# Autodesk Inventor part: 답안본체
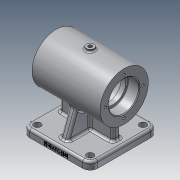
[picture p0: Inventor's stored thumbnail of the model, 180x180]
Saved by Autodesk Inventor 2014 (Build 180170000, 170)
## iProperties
Created: 2019-06
Part Number: 답안본체
Material: 알루미늄 6061
Document SubType Name: Modeling
Designer: net
Density: 2.71 g/cm^3
Appearance: 알루미늄 - 평지
Mass: 612.561 g
Surface Area: 622.973 cm^2
Volume: 226.037 cm^3
Author: net
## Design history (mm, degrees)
sketch "스케치1"
  geometry: C1 r 32 at (0, 0); 1 further point
  constraints: 1 centre point, 1 coincident
  dimensions: "d0" = 64 diameter of C1
extrude "돌출1" new body sketch "스케치1" stored distance "d1" = 90; taper "d2" = 0 deg
sketch "스케치2"
  geometry: L1 (-32, -45)-(32, -45) reference; L2 (32, 45)-(-32, 45) reference; L3 (0, 45)-(0, -45); L4 (0, 45)-(20, 45); L5 (20, 45)-(20, 30.6); L6 (19.4, 30)-(17, 30); L7 (17, 30)-(17, 24); L8 (17, 24)-(25, 24); L9 (25, 24)-(25, -24); L10 (25, -24)-(17, -24); L11 (17, -24)-(17, -30); L12 (17, -30)-(19.4, -30); L13 (20, -30.6)-(20, -45); L14 (20, -45)-(0, -45); A1 r 0.6 centre (19.4, 30.6) between (19.4, 30) and (20, 30.6); A2 r 0.6 centre (19.4, -30.6) between (20, -30.6) and (19.4, -30); 3 further points
  constraints: 24 end point, 6 parallel, 6 point on line, 4 point on circle, 4 tangent, 3 perpendicular, 2 centre point, 2 midpoint, 1 collinear, 1 equal radius
  dimensions: "d3" = 15 distance of L4.end point (20, 30); "d4" = 15 distance of point (20, -30) L13.end; "d5" = 6 distance of L10.end L11.end; "d6" = 6 distance of L6.end L7.end; "d7" = 40 diameter of L5 L3; "d8" = 40 diameter of L13 L3; "d9" = 34 diameter of L11 L3; "d10" = 34 diameter of L7 L3; "d11" = 50 diameter of L9 L3; "d12" = 0.6 radius of A1
revolve "회전1" sketch "스케치2" stored, may be unused: angle "d13" = 90 deg
chamfer "모따기1" distance "d14" = 1; stored, may be unused: second distance "d15" = 2, angle "d16" = 45 deg
node "작업 평면1"
sketch "스케치3"
  geometry: C1 r 5 at (0, 0); 1 further point
  constraints: 1 centre point, 1 coincident
  dimensions: "d18" = 10 diameter of C1
extrude "돌출2" join sketch "스케치3" stored distance "d19" = 90; taper "d20" = 0 deg
sketch "스케치4"
  geometry: C1 r 5 at (0, 0) reference; 1 further point
  constraints: 1 coincident
hole "구멍1" sketch "스케치4" at (0, 0) diameter "d21" = 4.917; stored, may be unused: countersink angle "d25" = 90 deg, drill point angle "d27" = 118 deg; dims "d22" = 6, "d23" = 4, "d24" = 2, "d26" = 20
fillet "모깎기1" dims "d28" = 2
sketch "스케치5"
  geometry: C1 r 32 at (0, 0) reference; 1 further point
  constraints: 1 horizontal alignment
  dimensions: "d29" = 25 distance of C1.centre point (-25, 0)
hole "구멍2" sketch "스케치5" at (-25, 0) diameter "d30" = 3.242; stored, may be unused: countersink angle "d34" = 90 deg, drill point angle "d36" = 118 deg; dims "d31" = 7, "d32" = 4, "d33" = 2, "d35" = 9
node "작업 평면2"
sketch "스케치6"
  geometry: L1 (45, 45)-(-45, 45); L2 (-45, 45)-(-45, -45); L3 (-45, -45)-(45, -45); L4 (45, -45)-(45, 45); L5 (45, 45)-(-45, -45); L6 (-45, 45)-(45, -45); 1 further point
  constraints: 12 end point, 2 midpoint, 2 parallel, 1 horizontal, 1 perpendicular
  dimensions: "d41" = 90 distance of L3.end L2.end; "d42" = 90 distance of L3.end L1.start
extrude "돌출3" join sketch "스케치6" distance "d43" = 10; taper "d44" = 0 deg
fillet "모깎기2" dims "d45" = 10
fillet "모깎기3" dims "d46" = 3
sketch "스케치7"
  geometry: C1 r 4.5 at (-35, 35); C2 r 4.5 at (-35, -35); C3 r 4.5 at (35, 35); C4 r 4.5 at (35, -35); A1 r 7 centre (35, -35) between (35, -42) and (42, -35) reference; A2 r 7 centre (35, 35) between (42, 35) and (35, 42) reference; A3 r 7 centre (-35, 35) between (-35, 42) and (-42, 35) reference; A4 r 7 centre (-35, -35) between (-42, -35) and (-35, -42) reference; 1 further point
  constraints: 4 centre point, 4 coincident
  dimensions: "d47" = 9 diameter of C1; "d48" = 9 diameter of C2; "d49" = 9 diameter of C3; "d50" = 9 diameter of C4
extrude "돌출4" cut sketch "스케치7" distance "d51" = 10; taper "d52" = 0 deg
sketch "스케치8"
  geometry: L1 (-5, 35)-(5, 35); L2 (5, 35)-(5, -35); L3 (5, -35)-(-5, -35); L4 (-5, -35)-(-5, 35); L5 (-35, -45)-(35, -45) reference; 2 further points
  constraints: 8 end point, 2 parallel, 1 horizontal, 1 midpoint, 1 perpendicular, 1 vertical alignment
  dimensions: "d53" = 10 distance of L2.end L3.end; "d54" = 10 distance between parallel lines of L5 L3; "d55" = 70 distance between parallel lines of L1 L3
extrude "돌출5" join sketch "스케치8" stored distance "d56" = 10; taper "d57" = 0 deg
sketch "스케치9"
  geometry: L1 (-39.5, -55)-(-30.5, -55) reference; L2 (-35, -55)-(35, -55) reference; L3 (-35, -55)-(-23.058, -22.189); L4 (-45, -65)-(-45, -58) reference; 2 further points
  constraints: 2 end point, 1 midpoint, 2 other
  dimensions: "d58" = 10 distance from line of L4 L3.start; "d59" = 110 deg angle of L1 L3
feature "리브1" sketch "스케치9" dims "d60" = 10, "d61" = 10, "d62" = 0, "d63" = 0, "d64" = 1, "d65" = 1
fillet "모깎기4" dims "d66" = 3
fillet "모깎기5" dims "d67" = 3
fillet "모깎기6" dims "d68" = 3
sketch "스케치10"
  geometry: L1 (-35, 45)-(35, 45) reference; L2 (-40, -22.053)-(-40, 22.053); L3 (-37, 25.053)-(-35.053, 25.053); L4 (-25.053, 35.053)-(-25.053, 37); L5 (-22.053, 40)-(22.053, 40); L6 (25.053, 37)-(25.053, 35.053); L7 (35.053, 25.053)-(37, 25.053); L8 (40, 22.053)-(40, -22.053); L9 (37, -25.053)-(35.053, -25.053); L10 (25.053, -35.053)-(25.053, -37); L11 (22.053, -40)-(-22.053, -40); L12 (-25.053, -37)-(-25.053, -35.053); L13 (-35.053, -25.053)-(-37, -25.053); A1 r 10 centre (-35, -35) between (-45, -35) and (-35, -45) reference; A2 r 10 centre (35, -35) between (35, -45) and (45, -35) reference; A3 r 10 centre (35, 35) between (45, 35) and (35, 45) reference; A4 r 10 centre (-35, 35) between (-35, 45) and (-45, 35) reference; A5 r 10 centre (-35, 35) between (-36.026, 25.053) and (-25.053, 36.026); A6 r 10 centre (35, 35) between (25.053, 36.026) and (36.026, 25.053); A7 r 10 centre (-35, -35) between (-25.053, -36.026) and (-36.026, -25.053); A8 r 10 centre (35, -35) between (36.026, -25.053) and (25.053, -36.026); A9 r 10 centre (-35.053, 35.053) between (-35.053, 25.053) and (-25.053, 35.053); A10 r 10 centre (35.053, 35.053) between (25.053, 35.053) and (35.053, 25.053); A11 r 10 centre (35.053, -35.053) between (35.053, -25.053) and (25.053, -35.053); A12 r 10 centre (-35.053, -35.053) between (-25.053, -35.053) and (-35.053, -25.053); A13 r 3 centre (-37, 22.053) between (-37, 25.053) and (-40, 22.053); A14 r 3 centre (-22.053, 37) between (-22.053, 40) and (-25.053, 37); A15 r 3 centre (22.053, 37) between (25.053, 37) and (22.053, 40); A16 r 3 centre (37, 22.053) between (40, 22.053) and (37, 25.053); A17 r 3 centre (37, -22.053) between (37, -25.053) and (40, -22.053); A18 r 3 centre (22.053, -37) between (22.053, -40) and (25.053, -37); A19 r 3 centre (-37, -22.053) between (-40, -22.053) and (-37, -25.053); A20 r 3 centre (-22.053, -37) between (-25.053, -37) and (-22.053, -40); 1 further point
  constraints: 32 point on circle, 24 end point, 24 tangent, 16 centre point, 10 equal radius, 9 parallel, 8 midpoint, 4 coincident, 2 perpendicular, 1 collinear
  dimensions: "d69" = 80 distance between parallel lines of L11 L5; "d70" = 40 distance from line of L5 point (0, 0); "d71" = 80 distance between parallel lines of L2 L8; "d72" = 40 distance from line of L2 point (0, 0); "d73" = 20 diameter of A5; "d74" = 20 diameter of A6; "d75" = 20 diameter of A7; "d76" = 20 diameter of A8; "d77" = 10 radius of A9; "d78" = 3 radius of A13
extrude "돌출6" cut sketch "스케치10" distance "d79" = 5; taper "d80" = 0 deg
sketch "스케치11"
  geometry: L1 (0, 0)-(70, 0) reference; L2 (-10, 7)-(-10, 0) reference; 2 further points
  constraints: 1 other
  dimensions: "d81" = 4 distance from line of L1 point (35, 4); "d82" = 45 distance from line of L2 point (35, 4)
feature "엠보싱1" sketch "스케치11" dims "d3" = 15, "d4" = 15, "d5" = 6, "d6" = 6, "d7" = 40, "d8" = 40, "d9" = 34, "d10" = 34, "d11" = 50, "d12" = 0.6, "d83" = 0.5, "d84" = 0
node "솔리드1"
pattern_circular "원형 패턴1" dims angle "d38" = 360 deg
mirror "대칭1"
mirror "대칭2"
node "투영된 루프1"
other parameters: "d17" = 35, "d40" = -65
